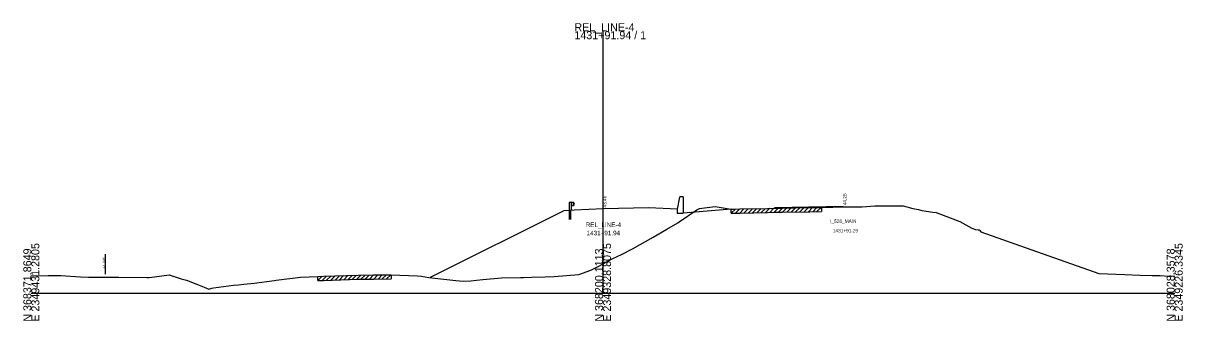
# Model space of a CAD drawing. Extents: x -26 to 2350146, y -10 to 368200.
# Drawn here: x 997.2 to 1402.8, y 6490.3 to 6594.4 of the extents above; entities that cross this region are included whole.
import ezdxf

# ---------------------------------------------------------------- set-up
doc = ezdxf.new("R2010")
doc.units = 0
for name, color, linetype in [('RD_GPK_XS_Cell', 7, 'Continuous'), ('RD_Sketch2', 7, 'Continuous'), ('RD_XS_EarthShd', 7, 'Continuous'), ('RD_XS_ExGround', 7, 'Continuous'), ('RD_XS_ExPaveRet', 7, 'Continuous'), ('RD_XS_ExRW', 7, 'Continuous'), ('RD_XS_GR', 7, 'Continuous'), ('RD_XS_MedBWall', 7, 'Continuous'), ('RD_XS_Pave', 7, 'Continuous'), ('RD_XS_PaveShd', 7, 'Continuous'), ('RD_XS_TieSlope', 7, 'Continuous'), ('RD_XS_TX_Elev_EX', 7, 'Continuous'), ('RD_XS_TX_Elev_PR', 7, 'Continuous'), ('RD_XS_TX_Station', 7, 'Continuous')]:
    doc.layers.add(name, color=color, linetype=linetype)

msp = doc.modelspace()

# ---------------------------------------------------------------- linework, layer by layer
at = {"layer": 'RD_GPK_XS_Cell'}
for p, q in [((1200, 6500), (1200, 6591.61)), ((1000, 6500), (1200, 6500)), ((1200, 6500), (1400, 6500))]:
    msp.add_line(p, q, dxfattribs=at)
at = {"layer": 'RD_Sketch2'}
msp.add_line((1284, 6530.25), (1260.01, 6529.78), dxfattribs=at)
at = {"layer": 'RD_XS_EarthShd'}
for p, q in [((1190, 6529.06), (1186.25, 6528.76)), ((1244.85, 6529.34), (1228, 6527.99))]:
    msp.add_line(p, q, dxfattribs=at)
at = {"layer": 'RD_XS_ExGround'}
msp.add_lwpolyline([(1000, 6506.02), (1005.88, 6506.21), (1010.33, 6506.21), (1017.25, 6505.71), (1020.01, 6505.6), (1023.82, 6505.57), (1030.6, 6505.61), (1040.41, 6505.51), (1041.22, 6505.51), (1043.06, 6505.73), (1048.26, 6506.36), (1052.48, 6505.03), (1054.25, 6504.5), (1058.19, 6503.05), (1060.44, 6502.04), (1062.05, 6501.38), (1063.12, 6501.68), (1063.73, 6501.82), (1070.74, 6502.81), (1072.44, 6502.92), (1074.35, 6503.11), (1077.92, 6503.5), (1085.11, 6504.44), (1085.63, 6504.5), (1094.19, 6505.53), (1100.29, 6505.83), (1102.24, 6505.89), (1114.32, 6506.25), (1119.86, 6506.33), (1125.91, 6506.4), (1131.99, 6506.19), (1135.06, 6506.02), (1136.51, 6505.89), (1139.11, 6505.5), (1148.49, 6504.46), (1151.04, 6504.12), (1153.78, 6504.33), (1155.69, 6504.5), (1157.93, 6504.74), (1164.54, 6505.38), (1171.16, 6505.5), (1172.18, 6505.5), (1175, 6505.57), (1179.72, 6505.63), (1182.97, 6505.81), (1191.52, 6506.53), (1195.73, 6508.04), (1198.35, 6509.28), (1200, 6510.19), (1201.92, 6511.25), (1203.45, 6512.08), (1206.45, 6513.51), (1210.27, 6515.54), (1217.58, 6519.57), (1222.35, 6522.33), (1226.15, 6524.55), (1226.7, 6524.91), (1232.82, 6529.14), (1233.72, 6529.64), (1235.49, 6529.87), (1238.29, 6530.13), (1239.28, 6530.28), (1244.18, 6529.46), (1244.85, 6529.34), (1245.66, 6529.36), (1248.03, 6529.43), (1257.58, 6529.64), (1260.12, 6529.7), (1262.72, 6529.74), (1272.4, 6529.89), (1276.49, 6529.99), (1276.7, 6529.99), (1280.46, 6530.09), (1283.43, 6530.16), (1286.96, 6530.16), (1290.63, 6530.19), (1295.06, 6530.51), (1296.66, 6530.52), (1302.36, 6530.54), (1304.97, 6530.53), (1308.39, 6529.6), (1310.35, 6529.29), (1311.53, 6528.9), (1315.38, 6528.3), (1316.54, 6528.14), (1318.98, 6527.25), (1324.8, 6525.04), (1329, 6522.73), (1330.33, 6522.23), (1331.19, 6522.14), (1331.54, 6522.17), (1331.7, 6521.98), (1332.13, 6521.42), (1373.42, 6506.81), (1382.54, 6506.52), (1387.8, 6506.29), (1392.07, 6506.17), (1394.97, 6506.14), (1397.83, 6505.97), (1398.14, 6505.96), (1398.3, 6506.03), (1398.65, 6506.01), (1400, 6505.89)], dxfattribs=at)
at = {"layer": 'RD_XS_ExPaveRet'}
for p, q in [((1244.85, 6527.9), (1246.33, 6529.38)), ((1244.85, 6527.9), (1244.85, 6529.34)), ((1244.85, 6527.9), (1245.66, 6527.92)), ((1245.66, 6527.92), (1248.03, 6528)), ((1246.35, 6527.94), (1247.84, 6529.43)), ((1247.85, 6527.99), (1249.32, 6529.46)), ((1248.03, 6528), (1257.58, 6528.2)), ((1249.35, 6528.03), (1250.82, 6529.49)), ((1250.85, 6528.06), (1252.32, 6529.53)), ((1252.35, 6528.09), (1253.82, 6529.56)), ((1253.85, 6528.12), (1255.32, 6529.59)), ((1255.35, 6528.16), (1256.82, 6529.63)), ((1256.85, 6528.19), (1258.32, 6529.66)), ((1257.58, 6528.2), (1260.12, 6528.26)), ((1258.35, 6528.22), (1259.82, 6529.69)), ((1259.85, 6528.26), (1261.32, 6529.72)), ((1260.12, 6528.26), (1262.72, 6528.31)), ((1261.35, 6528.28), (1262.82, 6529.75)), ((1262.72, 6528.31), (1272.4, 6528.45)), ((1262.85, 6528.31), (1264.31, 6529.77)), ((1264.35, 6528.33), (1265.81, 6529.79)), ((1265.85, 6528.36), (1267.31, 6529.81)), ((1267.35, 6528.38), (1268.81, 6529.84)), ((1268.85, 6528.4), (1270.31, 6529.86)), ((1270.35, 6528.42), (1271.81, 6529.88)), ((1271.85, 6528.45), (1273.32, 6529.91)), ((1272.4, 6528.45), (1276.49, 6528.55)), ((1273.35, 6528.48), (1274.82, 6529.95)), ((1274.85, 6528.51), (1276.32, 6529.98)), ((1276.49, 6529.99), (1276.49, 6528.55)), ((1100.29, 6504.39), (1101.78, 6505.88)), ((1100.29, 6504.39), (1100.29, 6505.83)), ((1100.29, 6504.39), (1102.24, 6504.46)), ((1101.79, 6504.44), (1103.28, 6505.92)), ((1102.24, 6504.46), (1114.32, 6504.82)), ((1103.29, 6504.49), (1104.77, 6505.97)), ((1104.79, 6504.53), (1106.27, 6506.01)), ((1106.29, 6504.58), (1107.77, 6506.06)), ((1107.79, 6504.62), (1109.27, 6506.1)), ((1109.29, 6504.67), (1110.77, 6506.15)), ((1110.79, 6504.71), (1112.27, 6506.19)), ((1112.29, 6504.76), (1113.77, 6506.24)), ((1113.79, 6504.8), (1115.26, 6506.27)), ((1114.32, 6504.82), (1119.86, 6504.89)), ((1115.29, 6504.83), (1116.75, 6506.29)), ((1116.79, 6504.85), (1118.25, 6506.31)), ((1118.29, 6504.87), (1119.75, 6506.33)), ((1119.79, 6504.89), (1121.25, 6506.34)), ((1119.86, 6504.89), (1125.91, 6504.96)), ((1121.29, 6504.91), (1122.75, 6506.36)), ((1122.79, 6504.93), (1124.25, 6506.38)), ((1124.29, 6504.94), (1125.75, 6506.4)), ((1125.91, 6506.4), (1125.91, 6504.96))]:
    msp.add_line(p, q, dxfattribs=at)
at = {"layer": 'RD_XS_ExRW'}
msp.add_line((1025.91, 6506.58), (1025.91, 6513.58), dxfattribs=at)
at = {"layer": 'RD_XS_GR'}
for p, q in [((1188.14, 6531.71), (1188.14, 6528.91)), ((1188.81, 6531.71), (1188.14, 6531.71)), ((1188.81, 6531.71), (1188.81, 6528.96)), ((1189.73, 6531.71), (1188.81, 6531.71)), ((1189.73, 6530.54), (1189.73, 6531.71)), ((1189.73, 6531.64), (1189.89, 6531.44)), ((1188.14, 6529.1), (1188.14, 6525.69)), ((1188.8, 6525.69), (1188.8, 6529.16)), ((1189.73, 6530.54), (1188.81, 6530.54)), ((1189.89, 6531.39), (1189.73, 6531.19)), ((1189.89, 6530.86), (1189.73, 6531.06)), ((1189.73, 6530.61), (1189.89, 6530.81)), ((1189.89, 6531.44), (1189.89, 6531.39)), ((1189.89, 6530.81), (1189.89, 6530.86))]:
    msp.add_line(p, q, dxfattribs=at)
at = {"layer": 'RD_XS_MedBWall'}
for p, q in [((1226.79, 6533.53), (1226, 6529.38)), ((1227.16, 6533.65), (1226.91, 6533.65)), ((1228, 6533.65), (1227.16, 6533.65)), ((1228, 6533.65), (1228, 6527.99)), ((1226, 6529.38), (1226, 6527.99)), ((1226, 6527.99), (1228, 6527.99))]:
    msp.add_line(p, q, dxfattribs=at)
msp.add_ellipse((1226.91, 6533.51), major_axis=(0, -0.133), ratio=0.910156, start_param=3.141593, end_param=4.607459, dxfattribs=at)
at = {"layer": 'RD_XS_Pave'}
msp.add_line((1216, 6529.78), (1200, 6529.46), dxfattribs=at)
at = {"layer": 'RD_XS_PaveShd'}
for p, q in [((1200, 6529.46), (1190, 6529.06)), ((1226, 6529.38), (1216, 6529.78))]:
    msp.add_line(p, q, dxfattribs=at)
at = {"layer": 'RD_XS_TieSlope'}
msp.add_line((1186.25, 6528.76), (1139.59, 6505.43), dxfattribs=at)

# ---------------------------------------------------------------- texts
at = {"layer": 'RD_GPK_XS_Cell'}
for s, p in [('REL_LINE-4', (1190, 6591.61)), ('1431+91.94 / 1', (1190, 6588.81))]:
    msp.add_text(s, height=2.8, dxfattribs=at).set_placement(p)
for s, p in [('N 368371.8649', (1000, 6490)), ('E 2349431.2805', (1002.8, 6490)), ('N 368200.1113', (1200, 6490)), ('E 2349328.8075', (1202.8, 6490)), ('N 368028.3578', (1400, 6490)), ('E 2349226.3345', (1402.8, 6490))]:
    msp.add_text(s, height=2.8, rotation=90, dxfattribs=at).set_placement(p)
at = {"layer": 'RD_Sketch2'}
msp.add_text(' 44.25', height=1.2, rotation=90, dxfattribs=at).set_placement((1285.2, 6530.25))
for s, p in [('I_526_MAIN', (1279.49, 6524.55)), ('1431+91.29', (1280.4, 6521.25))]:
    msp.add_text(s, height=1.2, dxfattribs=at).set_placement(p)
at = {"layer": 'RD_XS_ExRW'}
msp.add_text('EX. R/W ', height=0.75, rotation=90, dxfattribs=at).set_placement((1025.66, 6508.53))
at = {"layer": 'RD_XS_TX_Elev_EX'}
msp.add_text('24.19', height=1, rotation=90, dxfattribs=at).set_placement((1200.5, 6510.19))
at = {"layer": 'RD_XS_TX_Elev_PR'}
msp.add_text(' 43.46', height=1.2, rotation=90, dxfattribs=at).set_placement((1201.2, 6529.46))
at = {"layer": 'RD_XS_TX_Station'}
for s, p in [('REL_LINE-4', (1193.93, 6523.11)), ('1431+91.94', (1194.26, 6520.21))]:
    msp.add_text(s, height=1.6, dxfattribs=at).set_placement(p)

doc.saveas('drawing.dxf')
